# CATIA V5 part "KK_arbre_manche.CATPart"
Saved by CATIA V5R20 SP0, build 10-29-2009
Part number: arbre_manche
Bounding box of the stored display mesh (mm): x -9.997 to 9.997, y 0 to 85, z -9.997 to 9.997
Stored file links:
  G:\Khaled_CFAO_2011\ST2M\ST2M_GR2\aandujar\Khaled\CAD_thinkMOTION\KK_arbre_manche.CATPart
  G:\Khaled_CFAO_2011\ST2M\ST2M_GR2\aandujar\Khaled\CAD_thinkMOTION\KK_Aandujar.CATProduct
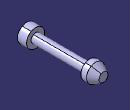
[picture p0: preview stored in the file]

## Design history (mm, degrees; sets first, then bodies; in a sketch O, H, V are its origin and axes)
WSupportSet1: ActiveGrid {3dwsupport RefPoint {point stored without definition}, 3DWOS ({wsupport Support xy-plane, RefPoint {3dwsupport}, GridIn {cartgrid Value 100, Stepbid1 0, Value 100, Stepbid2 0, Direction (1, 0, 0)}, GeometricData ({line type PtDir, Direction (1, 0, 0), Support xy-plane}; {line type PtDir, Direction (0, 1, 0), Support yz-plane})}; {wsupport Support yz-plane, RefPoint {3dwsupport}, GridIn {cartgrid Value 100, Stepbid1 0, Value 100, Stepbid2 0, Direction (0, 1, 0)}, GeometricData ({line type PtDir, Direction (0, 1, 0), Support yz-plane}; {line type PtDir, Direction (0, 0, 1), Support zx-plane})}; {wsupport Support zx-plane, RefPoint {3dwsupport}, GridIn {cartgrid Value 100, Stepbid1 0, Value 100, Stepbid2 0, Direction (0, 0, 1)}, GeometricData ({line type PtDir, Direction (0, 0, 1), Support zx-plane}; {line type PtDir, Direction (1, 0, 0), Support xy-plane})}), GeometricData ({line type PtDir, RefPoint {point stored without definition}, Direction (1, 0, 0), Support xy-plane}; {line type PtDir, RefPoint {point stored without definition}, Direction (0, 1, 0), Support yz-plane}; {line type PtDir, RefPoint {point stored without definition}, Direction (0, 0, 1), Support zx-plane})}
Set1
  Plane1 "Plan_Ref1": linked copy from another document
  Point1: linked copy from another document
  Point2: linked copy from another document
Body1 (main body)
  Sketch1 on Plane1, origin (0, 0, 0), H (0, 1, 0), V (0, 0, 1)
    point P1 (0, 0)
    line L1 (76.3397, 10) -> (85, 5)
    line L2 (85, 5) -> (85, 0)
    point P4 (85, 0)
    line L3 (85, 0) -> (0, 0)
    reference projected point E1 (0, 0) from Point1
    reference projected point E2 (85, 0) from Point2
    line L4 (76.3397, 10) -> (70, 10)
    line L5 (70, 10) -> (70, 5)
    line L6 (70, 5) -> (10, 5)
    line L7 (10, 5) -> (10, 10)
    point P8 (10, 10)
    line L8 (10, 10) -> (0, 10)
    point P9 (0, 10)
    line L9 (0, 10) -> (0, 0)
    angle L1 L3 = 30
    length L1 = 10
    length L2 = 5
    length L5 = 5
    distance L2 L5 = 15
    distance L7 L9 = 10
    vertical: L2 V, L5 V, L7 V, L9 V
    horizontal: L3 H, L4 H, L6 H, L8 H
    coincidence: P1 E1, E2 P4, P8 L4, P9 V
  Shaft1: profile Sketch1, axis Sketch1.L3, angle 360
  Sketch2 on face of Shaft1 from Sketch1.L9, origin (0, 0, 0), H (1, 0, 0), V (0, 0, 1)
    circle A1 centre (0, 0) radius 7.5
    radius A1 = 7.5
  Pocket1: profile Sketch2, direction (0, 1, 0), length 5
  Sketch3 on end face of Pocket1, origin (0, 5, 0), H (1, 0, 0), V (0, 0, 1)
    circle A1 centre (0, 0) radius 5
    radius A1 = 5
  Pad1: profile Sketch3, direction (0, -1, 0), length 5
  Sketch4 on end face of Pad1, origin (0, 0, 0), H (1, 0, 0), V (0, 0, 1)
    line L1 (-2.5, 2.5) -> (2.5, 2.5)
    line L2 (2.5, 2.5) -> (2.5, -2.5)
    line L3 (2.5, -2.5) -> (-2.5, -2.5)
    line L4 (-2.5, -2.5) -> (-2.5, 2.5)
    distance L2 V = 2.5
    distance L4 V = 2.5
    distance L3 H = 2.5
    distance L1 H = 2.5
    horizontal: L1 H, L3 H
    vertical: L2 V, L4 V
  Pocket2: profile Sketch4, direction (0, 1, 0), length 5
